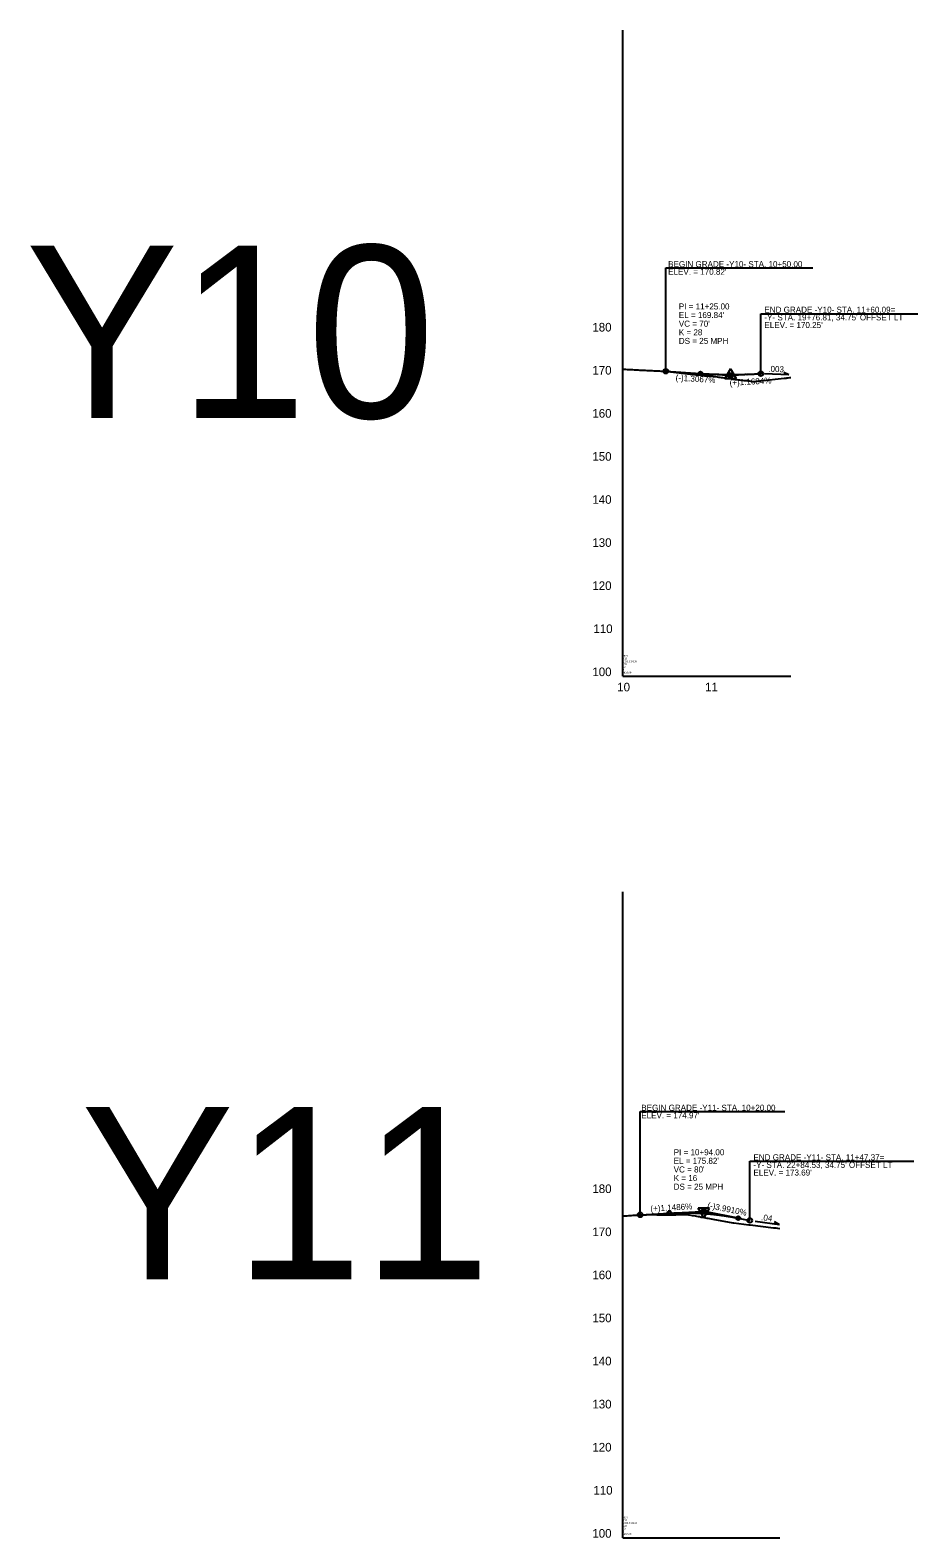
# Model space of a CAD drawing. Extents: x 1778432 to 1784301, y 601022 to 621789.
# Drawn here: x 1779455 to 1780485, y 607039 to 608789 of the extents above; entities that cross this region are included whole.
import ezdxf

# ---------------------------------------------------------------- set-up
doc = ezdxf.new("R2010")
doc.units = 0
for name, color, linetype in [('Exist Profile Cell', 7, 'Continuous'), ('Exist Vertical Profile Ground Line', 7, 'Continuous'), ('Exist Vertical Profile Horizontal Axis Label Major', 7, 'Continuous'), ('Exist Vertical Profile Vertical Axis Label', 7, 'Continuous'), ('Prop PFL Text', 7, 'Continuous'), ('Prop PFL VPI Symbol CELL', 7, 'Continuous'), ('Prop Vertical Profile Curve Label', 7, 'Continuous'), ('Prop Vertical Profile Grade', 7, 'Continuous'), ('Prop Vertical Profile Grade Label', 7, 'Continuous'), ('Prop VPI Label', 7, 'Continuous')]:
    doc.layers.add(name, color=color, linetype=linetype)

msp = doc.modelspace()

# ---------------------------------------------------------------- linework, layer by layer
at = {"layer": 'Exist Profile Cell'}
for p, q in [((1780143, 608039.2), (1780143, 608789.2)), ((1780143, 608039.2), (1780337.8, 608039.2)), ((1780143, 608039.2), (1780143, 608039.2)), ((1780143, 607039.2), (1780143, 607789.2)), ((1780143, 607039.2), (1780325.2, 607039.2)), ((1780143, 607039.2), (1780143, 607039.2))]:
    msp.add_line(p, q, dxfattribs=at)
at = {"layer": 'Exist Vertical Profile Ground Line'}
for points in [[(1780143, 608395.7), (1780144.6, 608395.6), (1780146.2, 608395.6), (1780147.9, 608395.5), (1780149.4, 608395.5), (1780151.1, 608395.4), (1780152.8, 608395.3), (1780154.4, 608395.2), (1780156, 608395.1), (1780157.6, 608395), (1780159.3, 608394.9), (1780160.9, 608394.8), (1780162.5, 608394.7), (1780164.2, 608394.6), (1780165.8, 608394.6), (1780167.4, 608394.5), (1780169.1, 608394.4), (1780170.7, 608394.3), (1780172.3, 608394.2), (1780174, 608394.1), (1780175.6, 608394.1), (1780177.2, 608394), (1780178.9, 608393.9), (1780180.5, 608393.8), (1780182.1, 608393.8), (1780183.8, 608393.7), (1780185.4, 608393.6), (1780187, 608393.5), (1780188.6, 608393.5), (1780190.3, 608393.4), (1780191.9, 608393.3), (1780192.4, 608393.3), (1780193.5, 608393.2), (1780194.2, 608393.2), (1780195.2, 608393), (1780196.8, 608392.9), (1780198.4, 608392.7), (1780200.1, 608392.5), (1780201.7, 608392.3), (1780203.3, 608392.1), (1780205, 608391.9), (1780206.6, 608391.7), (1780208.2, 608391.5), (1780209.9, 608391.3), (1780211.5, 608391.1), (1780213.1, 608391), (1780214.8, 608390.8), (1780216.6, 608390.6), (1780218, 608390.4), (1780219.7, 608390.2), (1780221.3, 608390), (1780222.9, 608389.9), (1780224.5, 608389.7), (1780226.2, 608389.5), (1780227.8, 608389.3), (1780229.4, 608389.2), (1780231.1, 608389), (1780232.7, 608388.8), (1780234.3, 608388.7), (1780236, 608388.5), (1780237.6, 608388.3), (1780239.2, 608388.2), (1780240.9, 608388), (1780242.5, 608387.9), (1780244.1, 608387.7), (1780245.8, 608387.5), (1780247.4, 608387.4), (1780248.5, 608387.3), (1780249.3, 608387.2), (1780250.7, 608387), (1780252.3, 608386.8), (1780253.9, 608386.6), (1780255.6, 608386.3), (1780257.2, 608386.1), (1780258.8, 608385.9), (1780260.4, 608385.7), (1780262.1, 608385.5), (1780263.8, 608385.2), (1780265.6, 608384.8), (1780267, 608384.7), (1780268.6, 608384.5), (1780270.2, 608384.2), (1780271.9, 608384), (1780273.5, 608383.8), (1780275.1, 608383.6), (1780276.8, 608383.4), (1780278.4, 608383.3), (1780280, 608383.1), (1780281.7, 608382.9), (1780283.3, 608382.7), (1780284.9, 608382.5), (1780286.6, 608382.4), (1780288.2, 608382.2), (1780289.6, 608382), (1780291.4, 608381.8), (1780293.1, 608381.5), (1780294.7, 608381.4), (1780296.3, 608381.5), (1780301.6, 608382.1), (1780302.7, 608382.2), (1780330.4, 608385.1), (1780331.8, 608385.2), (1780332.2, 608385.3), (1780333.1, 608385.4), (1780333.5, 608385.5), (1780334.8, 608385.6), (1780336.9, 608385.9), (1780337.3, 608385.9), (1780337.8, 608385.9)], [(1780143, 607412.8), (1780144.7, 607412.9), (1780146.4, 607413), (1780148.1, 607413.1), (1780149.8, 607413.3), (1780151.5, 607413.4), (1780153.2, 607413.5), (1780155, 607413.6), (1780155.6, 607413.6), (1780156.7, 607413.7), (1780158.4, 607413.8), (1780160.1, 607413.9), (1780161.8, 607414), (1780163.5, 607414.1), (1780165.2, 607414.2), (1780166.9, 607414.3), (1780167.6, 607414.3), (1780168.7, 607414.3), (1780170.4, 607414.3), (1780172.1, 607414.4), (1780173.8, 607414.4), (1780175.4, 607414.4), (1780177.2, 607414.4), (1780178.9, 607414.4), (1780180.7, 607414.4), (1780182.4, 607414.3), (1780184.1, 607414.3), (1780185.8, 607414.3), (1780187.5, 607414.3), (1780188.6, 607414.3), (1780189.2, 607414.3), (1780190.9, 607414.3), (1780192.7, 607414.3), (1780194.4, 607414.3), (1780196.1, 607414.3), (1780197.8, 607414.3), (1780199.5, 607414.3), (1780201.2, 607414.3), (1780202.9, 607414.3), (1780204.6, 607414.3), (1780206.4, 607414.4), (1780208.1, 607414.4), (1780209.8, 607414.4), (1780211.5, 607414.4), (1780213.2, 607414.4), (1780214.9, 607414.4), (1780216.6, 607414.4), (1780217.8, 607414.5), (1780218.6, 607414.4), (1780219.7, 607414.3), (1780220.1, 607414.2), (1780221.8, 607413.9), (1780223.5, 607413.5), (1780225.2, 607413.2), (1780226.9, 607412.9), (1780228.6, 607412.6), (1780230.3, 607412.3), (1780232.1, 607412), (1780233.8, 607411.6), (1780235.5, 607411.3), (1780237.2, 607411), (1780238.9, 607410.7), (1780240.6, 607410.4), (1780241.4, 607410.3), (1780241.7, 607410.2), (1780247.6, 607409.2), (1780270.5, 607405), (1780271.2, 607404.8), (1780271.7, 607404.7), (1780289.4, 607402.4), (1780289.8, 607402.5), (1780290.6, 607402.5), (1780317.9, 607399.2), (1780319.6, 607399), (1780320.2, 607399), (1780320.6, 607398.9), (1780322.6, 607398.7), (1780325.2, 607398.4)]]:
    msp.add_lwpolyline(points, dxfattribs=at)
at = {"layer": 'Prop PFL VPI Symbol CELL'}
for p, q in [((1780268, 608395.9), (1780261.5, 608384.7)), ((1780268, 608395.9), (1780274.5, 608384.7)), ((1780261.5, 608384.7), (1780274.5, 608384.7)), ((1780237, 607410.8), (1780230.5, 607422)), ((1780243.4, 607422), (1780230.5, 607422)), ((1780237, 607410.8), (1780243.4, 607422))]:
    msp.add_line(p, q, dxfattribs=at)
for centre, radius in [((1780268, 608388.4), 1.75), ((1780268, 608388.4), 1.2), ((1780237, 607418.3), 1.75), ((1780237, 607418.3), 1.2)]:
    msp.add_circle(centre, radius, dxfattribs=at)
at = {"layer": 'Prop Vertical Profile Curve Label'}
for centre in [(1780233, 608390.7), (1780303, 608390.4), (1780197, 607416), (1780277, 607410.3)]:
    msp.add_circle(centre, 2.25, dxfattribs=at)
at = {"layer": 'Prop Vertical Profile Grade'}
for p, q in [((1780193, 608393.3), (1780233, 608390.7)), ((1780303, 608390.4), (1780303, 608390.4)), ((1780163, 607414.1), (1780197, 607416)), ((1780277, 607410.3), (1780290.3, 607407.6))]:
    msp.add_line(p, q, dxfattribs=at)
for points in [[(1780233, 608390.7), (1780234.4, 608390.6), (1780235.8, 608390.5), (1780237.2, 608390.4), (1780238.6, 608390.3), (1780240, 608390.2), (1780241.4, 608390.2), (1780242.8, 608390.1), (1780244.2, 608390), (1780245.6, 608390), (1780247, 608389.9), (1780248.4, 608389.9), (1780249.8, 608389.8), (1780251.2, 608389.8), (1780252.6, 608389.7), (1780254, 608389.7), (1780255.4, 608389.6), (1780256.8, 608389.6), (1780258.2, 608389.6), (1780259.6, 608389.5), (1780261, 608389.5), (1780262.4, 608389.5), (1780263.8, 608389.5), (1780265.2, 608389.5), (1780266.6, 608389.5), (1780268, 608389.5), (1780269.4, 608389.5), (1780270.8, 608389.5), (1780272.2, 608389.5), (1780273.6, 608389.5), (1780275, 608389.5), (1780276.4, 608389.5), (1780277.8, 608389.5), (1780279.2, 608389.5), (1780280.6, 608389.6), (1780282, 608389.6), (1780283.4, 608389.6), (1780284.8, 608389.7), (1780286.2, 608389.7), (1780287.6, 608389.7), (1780289, 608389.8), (1780290.4, 608389.8), (1780291.8, 608389.9), (1780293.2, 608389.9), (1780294.6, 608390), (1780296, 608390.1), (1780297.4, 608390.1), (1780298.8, 608390.2), (1780300.2, 608390.3), (1780301.6, 608390.4), (1780303, 608390.4)], [(1780197, 607416), (1780198.6, 607416.1), (1780200.2, 607416.2), (1780201.8, 607416.2), (1780203.4, 607416.3), (1780205, 607416.3), (1780206.6, 607416.4), (1780208.2, 607416.4), (1780209.8, 607416.5), (1780211.4, 607416.5), (1780213, 607416.5), (1780214.6, 607416.5), (1780216.2, 607416.5), (1780217.8, 607416.5), (1780219.4, 607416.5), (1780221, 607416.4), (1780222.6, 607416.4), (1780224.2, 607416.4), (1780225.8, 607416.3), (1780227.4, 607416.2), (1780229, 607416.2), (1780230.6, 607416.1), (1780232.2, 607416), (1780233.8, 607415.9), (1780235.4, 607415.8), (1780237, 607415.7), (1780238.6, 607415.6), (1780240.2, 607415.5), (1780241.8, 607415.3), (1780243.4, 607415.2), (1780245, 607415), (1780246.6, 607414.9), (1780248.2, 607414.7), (1780249.8, 607414.5), (1780251.4, 607414.4), (1780253, 607414.2), (1780254.6, 607414), (1780256.2, 607413.8), (1780257.8, 607413.5), (1780259.4, 607413.3), (1780261, 607413.1), (1780262.6, 607412.8), (1780264.2, 607412.6), (1780265.8, 607412.3), (1780267.4, 607412.1), (1780269, 607411.8), (1780270.6, 607411.5), (1780272.2, 607411.2), (1780273.8, 607410.9), (1780275.4, 607410.6), (1780277, 607410.3)]]:
    msp.add_spline(points, degree=3, dxfattribs=at)
at = {"layer": 'Prop VPI Label'}
for p, q in [((1780193, 608393.3), (1780193, 608513.3)), ((1780193, 608513.3), (1780363.7, 608513.3)), ((1780303, 608390.4), (1780303, 608460.1)), ((1780303, 608460.1), (1780485.4, 608460.1)), ((1780233, 608390.7), (1780265.2, 608388.6)), ((1780303, 608390.4), (1780270.7, 608388.5)), ((1780335.7, 608389.3), (1780307.5, 608390.4)), ((1780335.7, 608389.3), (1780329.7, 608391.9)), ((1780163, 607414.1), (1780163, 607534.1)), ((1780163, 607534.1), (1780331.2, 607534.1)), ((1780290.3, 607407.6), (1780290.3, 607476.3)), ((1780290.3, 607476.3), (1780480.8, 607476.3)), ((1780197, 607416), (1780234.2, 607418.1)), ((1780277, 607410.3), (1780239.7, 607417.7)), ((1780324.7, 607402.7), (1780296.7, 607406.2)), ((1780324.7, 607402.7), (1780319, 607405.8))]:
    msp.add_line(p, q, dxfattribs=at)
for centre in [(1780193, 608393.3), (1780268, 608388.4), (1780303, 608390.4), (1780163, 607414.1), (1780237, 607418.3), (1780290.3, 607407.6)]:
    msp.add_circle(centre, 2.75, dxfattribs=at)

# ---------------------------------------------------------------- texts
at = {"layer": 'Exist Profile Cell'}
for s, p in [('Y10', (1780143, 608058.7)), ('RDY', (1780143, 608061.9)), ('1000.000000', (1780143, 608055.4)), ('2', (1780143, 608045.7)), ('100', (1780143, 608052.2)), ('10', (1780143, 608048.9)), ('NOGAP', (1780143, 608042.4)), ('Y11', (1780143, 607058.7)), ('RDY', (1780143, 607061.9)), ('2', (1780143, 607045.7)), ('1000.000000', (1780143, 607055.4)), ('100', (1780143, 607052.2)), ('10', (1780143, 607048.9)), ('NOGAP', (1780143, 607042.4))]:
    msp.add_text(s, height=2, dxfattribs=at).set_placement(p)
at = {"layer": 'Exist Vertical Profile Horizontal Axis Label Major'}
for s, p in [('10', (1780136.5, 608021.7)), ('11', (1780238.4, 608021.7))]:
    msp.add_text(s, height=10, dxfattribs=at).set_placement(p)
at = {"layer": 'Exist Vertical Profile Vertical Axis Label'}
for s, p in [('180', (1780107.6, 608439.4)), ('170', (1780107.6, 608389.4)), ('160', (1780107.6, 608339.4)), ('150', (1780107.6, 608289.4)), ('140', (1780107.6, 608239.4)), ('130', (1780107.6, 608189.4)), ('120', (1780107.6, 608139.4)), ('110', (1780108.8, 608089.4)), ('100', (1780107.6, 608039.4)), ('180', (1780107.6, 607439.4)), ('170', (1780107.6, 607389.4)), ('160', (1780107.6, 607339.4)), ('150', (1780107.6, 607289.4)), ('140', (1780107.6, 607239.4)), ('130', (1780107.6, 607189.4)), ('120', (1780107.6, 607139.4)), ('110', (1780108.8, 607089.4)), ('100', (1780107.6, 607039.4))]:
    msp.add_text(s, height=10, dxfattribs=at).set_placement(p)
at = {"layer": 'Prop PFL Text'}
for s, p in [('Y10', (1779449.3, 608339.2)), ('Y11', (1779513.8, 607339.2))]:
    msp.add_text(s, height=200, dxfattribs=at).set_placement(p)
at = {"layer": 'Prop Vertical Profile Curve Label'}
for s, p in [("VC = 70'", (1780208, 608445)), ('K = 28', (1780208, 608435)), ('DS = 25 MPH', (1780208, 608425)), ("VC = 80'", (1780202, 607463.3)), ('K = 16', (1780202, 607453.3)), ('DS = 25 MPH', (1780202, 607443.3))]:
    msp.add_text(s, height=7, dxfattribs=at).set_placement(p)
at = {"layer": 'Prop Vertical Profile Grade Label'}
for s, rotation, p in [('(-)1.3067%', 356.2653, (1780204.1, 608382.5)), ('.003', 357.8285, (1780311.7, 608392.7)), ('(+)1.1684%', 3.3762, (1780267.1, 608376.3)), ('(+)1.1486%', 3.2566, (1780175.2, 607417.8)), ('(-)3.9910%', 348.739, (1780240.6, 607422)), ('.04', 352.875, (1780303.2, 607407.9))]:
    msp.add_text(s, height=7, rotation=rotation, dxfattribs=at).set_placement(p)
at = {"layer": 'Prop VPI Label'}
for s, p in [('BEGIN GRADE -Y10- STA. 10+50.00', (1780195.6, 608514.1)), ("ELEV. = 170.82'", (1780195.6, 608505.2)), ('PI = 11+25.00', (1780208, 608465)), ("EL = 169.84'", (1780208, 608455)), ("-Y- STA. 19+76.81, 34.75' OFFSET LT", (1780307.3, 608452.3)), ('END GRADE -Y10- STA. 11+60.09=', (1780307.3, 608461.2)), ("ELEV. = 170.25'", (1780307.3, 608443.4)), ('BEGIN GRADE -Y11- STA. 10+20.00', (1780164.4, 607534.9)), ("ELEV. = 174.97'", (1780164.4, 607526.1)), ('PI = 10+94.00', (1780202, 607483.3)), ("EL = 175.82'", (1780202, 607473.3)), ('END GRADE -Y11- STA. 11+47.37=', (1780294.6, 607477.4)), ("-Y- STA. 22+84.53, 34.75' OFFSET LT", (1780294.6, 607468.6)), ("ELEV. = 173.69'", (1780294.6, 607459.7))]:
    msp.add_text(s, height=7, dxfattribs=at).set_placement(p)

doc.saveas('drawing.dxf')
